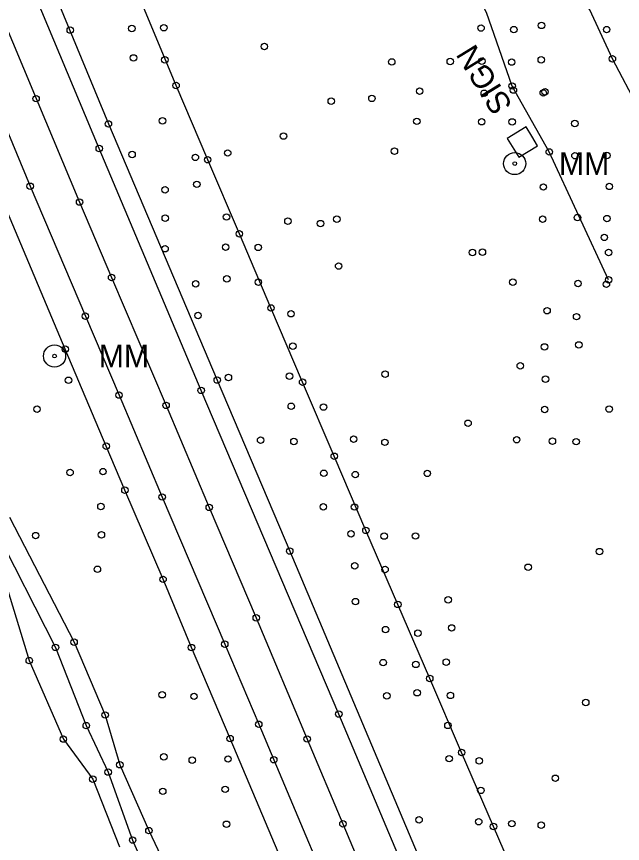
# Model space of a CAD drawing. Extents: x 20503438 to 20508873, y 7964251 to 7984667.
# Drawn here: x 20506012.3 to 20506200.2, y 7975825.9 to 7976082.3 of the extents above; entities that cross this region are included whole.
import ezdxf

# ---------------------------------------------------------------- set-up
doc = ezdxf.new("R2010")
doc.units = 0
for name, color, linetype in [('SurBreakLine', 7, 'Continuous'), ('SurDrainageArrowDown', 7, 'Continuous'), ('SurDrainageArrowUp', 7, 'Continuous'), ('SurEdgeRoadPaved', 7, 'Continuous'), ('SurEdgeShoulderPaved', 7, 'Continuous'), ('SurPointsNonDTM', 7, 'Continuous'), ('SurRoadPoints', 7, 'Continuous'), ('SurSurveyPoints', 7, 'Continuous')]:
    doc.layers.add(name, color=color, linetype=linetype)

msp = doc.modelspace()

# ---------------------------------------------------------------- linework, layer by layer
at = {"layer": 'SurBreakLine'}
for points in [[(20505865.6, 7976423.82), (20505881.11, 7976385.76), (20505895.61, 7976350.5), (20505907.36, 7976321.51), (20505912.71, 7976308.35), (20505920.59, 7976289.64), (20505936.63, 7976250.91), (20505952.01, 7976214.99), (20505962.56, 7976189.88), (20505976.58, 7976156.36), (20505989.8, 7976125.02), (20505999.68, 7976101.54), (20506018.4, 7976056.86), (20506031.88, 7976024.8), (20506041.81, 7976001.38), (20506058.69, 7975961.74), (20506072.07, 7975930.1), (20506086.64, 7975895.86), (20506102.43, 7975858.26), (20506113.52, 7975831.94), (20506128.17, 7975796.98)], [(20506321.91, 7975951.28), (20506292.04, 7975971.7), (20506276.55, 7975986.99), (20506267.72, 7975999.31), (20506246.1, 7976007.41), (20506225.53, 7976028.87), (20506205.19, 7976053.67), (20506197.03, 7976069.21), (20506190.03, 7976084.37), (20506184.41, 7976093.4), (20506177.2, 7976103.38), (20506168.01, 7976123.8)], [(20506010.18, 7975927.08), (20506030.18, 7975888.29), (20506039.82, 7975865.71), (20506044.34, 7975850.28), (20506053.38, 7975829.85), (20506063.47, 7975808.48)], [(20506003.63, 7975923.63), (20506016.28, 7975882.58), (20506026.85, 7975858.24), (20506035.97, 7975845.81), (20506044.28, 7975824.82)]]:
    msp.add_lwpolyline(points, dxfattribs=at)
at = {"layer": 'SurDrainageArrowDown'}
for points in [[(20506195.88, 7976000.66), (20506177.48, 7976040.33), (20506165.97, 7976060.78), (20506157.97, 7976083.56), (20506137.62, 7976124.34), (20506125.41, 7976143.13), (20506115.51, 7976162.83), (20506106.84, 7976185.5), (20506100.72, 7976204.22), (20506092.06, 7976228.8), (20506081.93, 7976251.94), (20506071.16, 7976278.18), (20506056.4, 7976317.29), (20506048.65, 7976334.89), (20506051.6, 7976339.7)], [(20506209.68, 7975716.34), (20506199.78, 7975739.3), (20506189.89, 7975762.26), (20506179.99, 7975785.21), (20506170.1, 7975808.17), (20506160.2, 7975831.13), (20506150.31, 7975854.09), (20506140.42, 7975877.04), (20506130.52, 7975900), (20506120.64, 7975922.96), (20506110.83, 7975945.96), (20506101.02, 7975968.95), (20506091.21, 7975991.95), (20506081.4, 7976014.94), (20506071.59, 7976037.93), (20506061.78, 7976060.93), (20506052.23, 7976084.03), (20506042.81, 7976107.19), (20506033.39, 7976130.35), (20506023.98, 7976153.51), (20506014.56, 7976176.66), (20506014.08, 7976177.84)]]:
    msp.add_lwpolyline(points, dxfattribs=at)
at = {"layer": 'SurDrainageArrowUp'}
msp.add_lwpolyline([(20506005.17, 7975924.32), (20506024.41, 7975886.68), (20506033.95, 7975862.42), (20506040.75, 7975848), (20506048.33, 7975826.92), (20506057.34, 7975806.17)], dxfattribs=at)
at = {"layer": 'SurEdgeRoadPaved'}
for points in [[(20506278.91, 7975465.84), (20506257.71, 7975518.12), (20506250.34, 7975536.21), (20506236.76, 7975569.18), (20506175.22, 7975717.06), (20506144.4, 7975789.63), (20506112.25, 7975866.01), (20506069.58, 7975966.38), (20506037.98, 7976041.41), (20506015.97, 7976094.11), (20505947.59, 7976255.69), (20505927.83, 7976303), (20505916.28, 7976330.64), (20505901.17, 7976367.49), (20505888.02, 7976400.52), (20505875.61, 7976430.87)], [(20505854.48, 7976420.23), (20505870.79, 7976380.67), (20505883.55, 7976349.04), (20505897.65, 7976314.07), (20505909.99, 7976284.1), (20505926.99, 7976243.04), (20505936.73, 7976219.88), (20505946.63, 7976196.12), (20505956.71, 7976171.82), (20505963.64, 7976155.35), (20505975.06, 7976128.28), (20505995.52, 7976079.78), (20506006.7, 7976053.21), (20506016.58, 7976029.7), (20506033.67, 7975989.39), (20506044.1, 7975964.93), (20506057.48, 7975933.32), (20506076.87, 7975887.68), (20506087.41, 7975862.83), (20506092.07, 7975851.84), (20506114.77, 7975798.09)], [(20506093.39, 7975823.17), (20506078.53, 7975858.38), (20506066.58, 7975886.62), (20506057.75, 7975907.79), (20506045.94, 7975935.43), (20506040.16, 7975949.09), (20506027.46, 7975979.19), (20506009.5, 7976021.69), (20505992.28, 7976062.56), (20505979.1, 7976093.75), (20505967.62, 7976121.21), (20505954.55, 7976152.2), (20505937.07, 7976194.25), (20505927.35, 7976217.39), (20505915.34, 7976246.07), (20505899.65, 7976283.07), (20505883.58, 7976322.17), (20505872.12, 7976349.6), (20505858.8, 7976382.12), (20505847.76, 7976409.43)]]:
    msp.add_lwpolyline(points, dxfattribs=at)
at = {"layer": 'SurEdgeShoulderPaved'}
msp.add_lwpolyline([(20505889.98, 7976411.65), (20505895.55, 7976397.9), (20505920.61, 7976336.44), (20505950.34, 7976264.44), (20506010.6, 7976121.59), (20506025.61, 7976085.79), (20506040.8, 7976049.02), (20506074.56, 7975969.59), (20506097.02, 7975916.55), (20506142.06, 7975809.67), (20506177.13, 7975727.28), (20506237.29, 7975584.09), (20506267.06, 7975511.74), (20506296.53, 7975437.96)], dxfattribs=at)
at = {"layer": 'SurPointsNonDTM'}
for centre in [(20506175.07, 7976079.57), (20506176.15, 7976058.99), (20506194.53, 7976013.84)]:
    msp.add_circle(centre, 1, dxfattribs=at)
at = {"layer": 'SurRoadPoints'}
msp.add_lwpolyline([(20506172.05, 7976045.19), (20506172.05, 7976045.19), (20506170.26, 7976048.11), (20506164.42, 7976044.52), (20506168, 7976038.68), (20506173.84, 7976042.26), (20506172.05, 7976045.18)], dxfattribs=at)
for centre, radius in [((20506166.76, 7976036.73), 3.43), ((20506166.76, 7976036.73), 0.571), ((20506024.11, 7975977.04), 3.43), ((20506024.11, 7975977.04), 0.571)]:
    msp.add_circle(centre, radius, dxfattribs=at)
at = {"layer": 'SurSurveyPoints'}
for centre in [(20506028.99, 7976078.13), (20506048.09, 7976078.62), (20506057.99, 7976078.86), (20506156.32, 7976078.76), (20506166.48, 7976078.27), (20506195.26, 7976078.27), (20506089.15, 7976073.05), (20506048.61, 7976069.5), (20506197.03, 7976069.21), (20506058.29, 7976068.9), (20506128.65, 7976068.25), (20506146.77, 7976068.39), (20506156.55, 7976068.5), (20506165.82, 7976068.2), (20506174.98, 7976068.9), (20506061.78, 7976060.93), (20506137.29, 7976059.19), (20506165.97, 7976060.78), (20506166.34, 7976059.52), (20506018.4, 7976056.86), (20506122.49, 7976056.94), (20506157.32, 7976058.53), (20506175.62, 7976058.64), (20506109.89, 7976056.1), (20506040.8, 7976049.02), (20506057.58, 7976049.99), (20506136.4, 7976049.83), (20506156.52, 7976049.7), (20506165.97, 7976049.65), (20506185.4, 7976049.15), (20506095.07, 7976045.27), (20506037.98, 7976041.41), (20506048.16, 7976039.55), (20506067.77, 7976038.65), (20506077.79, 7976040), (20506129.46, 7976040.57), (20506177.48, 7976040.33), (20506185.43, 7976039.17), (20506195.34, 7976039.24), (20506071.59, 7976037.93), (20506016.58, 7976029.7), (20506058.37, 7976028.58), (20506068.23, 7976030.29), (20506175.63, 7976029.46), (20506196.08, 7976029.64), (20506031.88, 7976024.8), (20506058.44, 7976019.81), (20506077.42, 7976020.16), (20506096.46, 7976018.86), (20506106.56, 7976018.12), (20506111.63, 7976019.48), (20506175.42, 7976019.48), (20506186.22, 7976019.97), (20506195.35, 7976019.67), (20506081.4, 7976014.94), (20506058.37, 7976010.32), (20506077.16, 7976010.81), (20506087.26, 7976010.74), (20506153.65, 7976009.14), (20506156.75, 7976009.25), (20506195.87, 7976009.16), (20506112.18, 7976004.95), (20506041.81, 7976001.38), (20506077.52, 7976001), (20506087.29, 7975999.96), (20506166.17, 7975999.96), (20506195.88, 7976000.66), (20506067.87, 7975999.43), (20506186.38, 7975999.54), (20506195.17, 7975999.29), (20506091.21, 7975991.95), (20506097.42, 7975990.15), (20506176.79, 7975991.1), (20506033.67, 7975989.39), (20506068.59, 7975989.62), (20506185.94, 7975989.24), (20506097.97, 7975980.09), (20506175.99, 7975979.87), (20506186.64, 7975980.49), (20506027.46, 7975979.19), (20506168.49, 7975974.01), (20506028.45, 7975969.52), (20506074.56, 7975969.59), (20506078.01, 7975970.38), (20506096.94, 7975970.8), (20506126.57, 7975971.41), (20506176.29, 7975969.87), (20506101.02, 7975968.95), (20506044.1, 7975964.93), (20506069.58, 7975966.38), (20506058.69, 7975961.74), (20506097.5, 7975961.46), (20506018.68, 7975960.55), (20506107.49, 7975961.21), (20506176.05, 7975960.45), (20506196.03, 7975960.59), (20506152.29, 7975956.2), (20506116.83, 7975951.27), (20506040.16, 7975949.09), (20506088, 7975950.93), (20506098.31, 7975950.52), (20506126.53, 7975950.27), (20506167.37, 7975951.08), (20506178.44, 7975950.63), (20506185.82, 7975950.49), (20506110.83, 7975945.96), (20506028.92, 7975940.93), (20506039.13, 7975941.19), (20506107.6, 7975940.68), (20506117.34, 7975940.26), (20506139.67, 7975940.65), (20506045.94, 7975935.43), (20506057.48, 7975933.32), (20506038.5, 7975930.38), (20506072.07, 7975930.1), (20506107.43, 7975930.27), (20506117.11, 7975930.22), (20506120.64, 7975922.96), (20506018.26, 7975921.36), (20506038.64, 7975921.6), (20506116.02, 7975921.88), (20506126.3, 7975921.2), (20506136.02, 7975921.23), (20506097.02, 7975916.55), (20506193.04, 7975916.4), (20506037.41, 7975910.91), (20506117.16, 7975911.98), (20506126.56, 7975910.85), (20506170.93, 7975911.54), (20506057.75, 7975907.79), (20506117.38, 7975900.87), (20506130.52, 7975900), (20506146.13, 7975901.42), (20506086.64, 7975895.86), (20506126.73, 7975892.19), (20506147.21, 7975892.72), (20506136.75, 7975891.09), (20506030.18, 7975888.29), (20506076.87, 7975887.68), (20506024.41, 7975886.68), (20506066.58, 7975886.62), (20506016.28, 7975882.58), (20506125.98, 7975881.96), (20506145.54, 7975882.11), (20506136.1, 7975881.4), (20506140.42, 7975877.04), (20506057.47, 7975871.99), (20506127.11, 7975871.67), (20506136.53, 7975872.61), (20506146.82, 7975871.78), (20506067.35, 7975871.5), (20506188.78, 7975869.57), (20506039.82, 7975865.71), (20506112.25, 7975866.01), (20506033.95, 7975862.42), (20506087.41, 7975862.83), (20506146.05, 7975862.48), (20506026.85, 7975858.24), (20506078.53, 7975858.38), (20506102.43, 7975858.26), (20506150.31, 7975854.09), (20506057.99, 7975852.72), (20506066.8, 7975851.69), (20506077.89, 7975852.07), (20506092.07, 7975851.84), (20506146.43, 7975852.16), (20506155.77, 7975851.49), (20506044.34, 7975850.28), (20506040.75, 7975848), (20506179.35, 7975846.1), (20506035.97, 7975845.81), (20506057.66, 7975842.03), (20506076.99, 7975842.66), (20506156.27, 7975842.33), (20506137.1, 7975833.21), (20506077.41, 7975831.83), (20506113.52, 7975831.94), (20506155.6, 7975832.62), (20506160.2, 7975831.13), (20506165.86, 7975832.01), (20506174.99, 7975831.56), (20506053.38, 7975829.85), (20506048.33, 7975826.92)]:
    msp.add_circle(centre, 1, dxfattribs=at)

# ---------------------------------------------------------------- texts
at = {"layer": 'SurRoadPoints'}
for s, rotation, p in [('SIGN', 121.5323, (20506166.25, 7976054.78)), ('MM', 360, (20506180.47, 7976033.23)), ('MM', 360, (20506037.82, 7975973.54))]:
    msp.add_text(s, height=6.995, rotation=rotation, dxfattribs=at).set_placement(p)

doc.saveas('drawing.dxf')
